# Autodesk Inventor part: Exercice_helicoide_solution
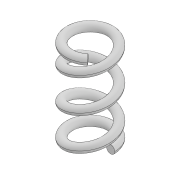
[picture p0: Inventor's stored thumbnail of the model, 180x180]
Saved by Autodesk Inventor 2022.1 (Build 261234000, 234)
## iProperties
Created: 2021-06
Part Number: Exercice_helicoide_solution
Material: Générique
Document SubType Name: Modeling
Designer: Fabian
Density: 1 g/cm^3
Appearance: Par défaut
Mass: 5.95432 g
Surface Area: 48.5135 cm^2
Volume: 5.95432 cm^3
Author: Fabian
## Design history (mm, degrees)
sketch "Esquisse1"
  geometry: L1 (0, 0)-(0, 14.18); C1 r 2.5 at (12.5, 0)
  constraints: 2 end point, 1 centre point, 1 vertical
  dimensions: "d0" = 5 diameter of C1; "d1" = 25 diameter of C1.centre L1
feature "Hélicoïde1" sketch "Esquisse1" pitch "d2" = 20; turns "d4" = 5; dims "d3" = 50, "d5" = 0, angle "d6" = 90 deg, angle "d7" = 200 deg, "d8" = 90 deg, "d9" = 200 deg
node "Solide1"
